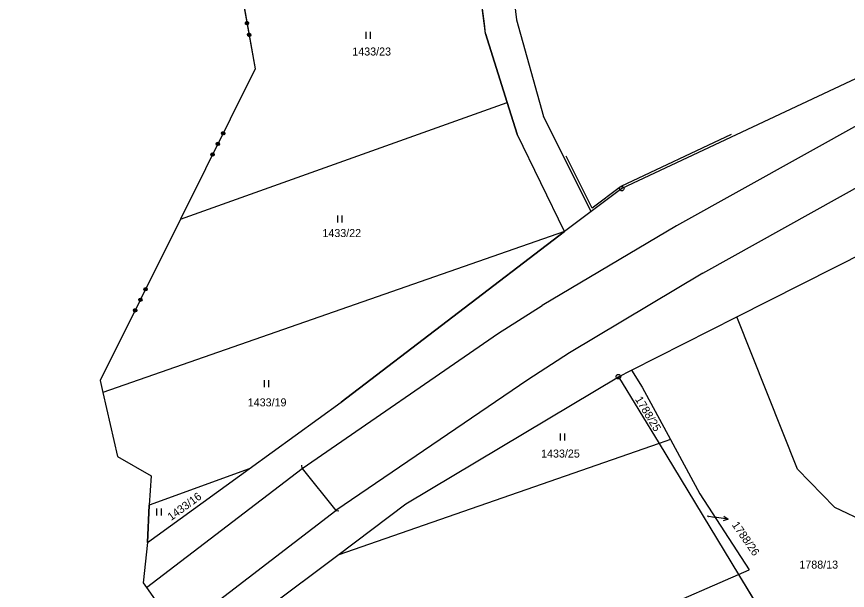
# Model space of a CAD drawing. Extents: x -779618 to -776429, y -1144546 to -1143350.
# Drawn here: x -779432.2 to -779255.7, y -1144160.9 to -1144039.1 of the extents above; entities that cross this region are included whole.
import ezdxf

# ---------------------------------------------------------------- set-up
doc = ezdxf.new("R2010")
doc.units = 0
for name, color, linetype in [('1', 7, 'Continuous'), ('11', 7, 'Continuous'), ('2', 7, 'Continuous'), ('3', 7, 'Continuous'), ('4', 7, 'Continuous'), ('7', 7, 'Continuous'), ('8', 7, 'Continuous')]:
    doc.layers.add(name, color=color, linetype=linetype)

msp = doc.modelspace()

# ---------------------------------------------------------------- linework, layer by layer
at = {"layer": '1'}
for p, q in [((-779333.51, -1143976.87), (-779326.02, -1144039.78)), ((-779332.56, -1144042.69), (-779336.07, -1144016.19)), ((-779384.98, -1144030.81), (-779381.47, -1144050.15)), ((-779326.02, -1144039.78), (-779320.25, -1144060.29)), ((-779332.56, -1144042.69), (-779327.95, -1144057.32)), ((-779234.67, -1144043.21), (-779303.65, -1144075.6)), ((-779381.47, -1144050.15), (-779397.35, -1144082.06)), ((-779397.35, -1144082.06), (-779327.95, -1144057.32)), ((-779327.95, -1144057.32), (-779325.83, -1144064.06)), ((-779310.15, -1144080.49), (-779320.25, -1144060.29)), ((-779315.83, -1144084.67), (-779325.83, -1144064.06)), ((-779303.65, -1144075.6), (-779310.15, -1144080.49)), ((-779310.15, -1144080.49), (-779315.83, -1144084.67)), ((-779279.24, -1144102.79), (-779234.73, -1144080.35)), ((-779397.35, -1144082.06), (-779414.4, -1144116.33)), ((-779315.83, -1144084.67), (-779413.82, -1144118.91)), ((-779315.83, -1144084.67), (-779363.24, -1144120.96)), ((-779301.59, -1144114.13), (-779279.24, -1144102.79)), ((-779266.31, -1144135.17), (-779279.24, -1144102.79)), ((-779304.36, -1144115.54), (-779301.59, -1144114.13)), ((-779301.59, -1144114.13), (-779299.29, -1144117.79)), ((-779349.51, -1144142.56), (-779304.36, -1144115.54)), ((-779304.36, -1144115.54), (-779295.74, -1144129.72)), ((-779414.4, -1144116.33), (-779413.82, -1144118.91)), ((-779299.29, -1144117.79), (-779293.27, -1144128.86)), ((-779413.82, -1144118.91), (-779410.76, -1144132.47)), ((-779382.76, -1144135.1), (-779363.24, -1144120.96)), ((-779295.74, -1144129.72), (-779363.98, -1144153.41)), ((-779293.27, -1144128.86), (-779295.74, -1144129.72)), ((-779295.74, -1144129.72), (-779278.85, -1144157.52)), ((-779293.27, -1144128.86), (-779287.1, -1144140.44)), ((-779410.76, -1144132.47), (-779403.56, -1144136.6)), ((-779404.34, -1144150.72), (-779382.76, -1144135.1)), ((-779382.76, -1144135.1), (-779404.03, -1144142.84)), ((-779266.31, -1144135.17), (-779258.5, -1144143.27)), ((-779403.56, -1144136.6), (-779404.03, -1144142.84)), ((-779287.1, -1144140.44), (-779276.58, -1144156.53)), ((-779363.98, -1144153.41), (-779349.51, -1144142.56)), ((-779404.34, -1144150.72), (-779404.03, -1144142.84)), ((-779258.5, -1144143.27), (-779243.97, -1144150.07)), ((-779404.34, -1144150.72), (-779405.26, -1144159.28)), ((-779393.54, -1144175.59), (-779363.98, -1144153.41)), ((-779278.85, -1144157.52), (-779276.58, -1144156.53)), ((-779298.22, -1144165.96), (-779278.85, -1144157.52)), ((-779278.85, -1144157.52), (-779271.48, -1144169.65)), ((-779405.26, -1144159.28), (-779404.55, -1144160.27)), ((-779404.55, -1144160.27), (-779398.38, -1144169.05))]:
    msp.add_line(p, q, dxfattribs=at)
for points in [[(-779382.89, -1144040.56), (-779383.04, -1144040.78), (-779383.3, -1144040.83), (-779383.52, -1144040.68), (-779383.57, -1144040.41), (-779383.42, -1144040.19), (-779383.15, -1144040.14), (-779382.93, -1144040.29), (-779382.89, -1144040.56), (-779382.93, -1144040.56), (-779382.97, -1144040.32), (-779383.06, -1144040.26), (-779382.99, -1144040.65), (-779383.06, -1144040.74), (-779383.16, -1144040.19), (-779383.23, -1144040.21), (-779383.13, -1144040.76), (-779383.21, -1144040.77), (-779383.31, -1144040.22), (-779383.39, -1144040.24), (-779383.29, -1144040.79), (-779383.38, -1144040.72), (-779383.46, -1144040.33), (-779383.52, -1144040.42), (-779383.48, -1144040.66)], [(-779382.44, -1144043.03), (-779382.59, -1144043.25), (-779382.86, -1144043.3), (-779383.08, -1144043.15), (-779383.12, -1144042.88), (-779382.97, -1144042.66), (-779382.71, -1144042.61), (-779382.48, -1144042.76), (-779382.44, -1144043.03), (-779382.48, -1144043), (-779382.53, -1144042.76), (-779382.62, -1144042.72), (-779382.55, -1144043.09), (-779382.61, -1144043.18), (-779382.7, -1144042.67), (-779382.78, -1144042.69), (-779382.69, -1144043.2), (-779382.77, -1144043.21), (-779382.86, -1144042.7), (-779382.94, -1144042.71), (-779382.85, -1144043.22), (-779382.94, -1144043.19), (-779383.01, -1144042.79), (-779383.08, -1144042.85), (-779383.04, -1144043.09)], [(-779388.07, -1144064.13), (-779388.32, -1144064.21), (-779388.56, -1144064.09), (-779388.65, -1144063.84), (-779388.53, -1144063.59), (-779388.28, -1144063.51), (-779388.03, -1144063.63), (-779387.95, -1144063.88), (-779388.07, -1144064.13), (-779388.11, -1144064.12), (-779388, -1144063.9), (-779388.04, -1144063.79), (-779388.22, -1144064.15), (-779388.31, -1144064.17), (-779388.07, -1144063.69), (-779388.15, -1144063.65), (-779388.38, -1144064.13), (-779388.46, -1144064.1), (-779388.22, -1144063.62), (-779388.29, -1144063.59), (-779388.53, -1144064.06), (-779388.58, -1144063.98), (-779388.39, -1144063.6), (-779388.49, -1144063.63), (-779388.61, -1144063.88)], [(-779389.19, -1144066.37), (-779389.44, -1144066.46), (-779389.68, -1144066.34), (-779389.77, -1144066.08), (-779389.65, -1144065.84), (-779389.39, -1144065.76), (-779389.15, -1144065.88), (-779389.07, -1144066.13), (-779389.19, -1144066.37), (-779389.22, -1144066.35), (-779389.11, -1144066.13), (-779389.15, -1144066.02), (-779389.32, -1144066.38), (-779389.43, -1144066.42), (-779389.18, -1144065.92), (-779389.25, -1144065.88), (-779389.5, -1144066.38), (-779389.57, -1144066.35), (-779389.33, -1144065.85), (-779389.4, -1144065.81), (-779389.65, -1144066.31), (-779389.68, -1144066.2), (-779389.5, -1144065.85), (-779389.61, -1144065.88), (-779389.72, -1144066.1)], [(-779390.3, -1144068.62), (-779390.56, -1144068.71), (-779390.8, -1144068.59), (-779390.89, -1144068.33), (-779390.77, -1144068.09), (-779390.51, -1144068), (-779390.27, -1144068.12), (-779390.18, -1144068.38), (-779390.3, -1144068.62), (-779390.32, -1144068.57), (-779390.21, -1144068.35), (-779390.26, -1144068.26), (-779390.43, -1144068.6), (-779390.54, -1144068.64), (-779390.3, -1144068.17), (-779390.38, -1144068.14), (-779390.61, -1144068.6), (-779390.68, -1144068.57), (-779390.45, -1144068.1), (-779390.51, -1144068.06), (-779390.75, -1144068.52), (-779390.8, -1144068.45), (-779390.62, -1144068.08), (-779390.71, -1144068.09), (-779390.82, -1144068.31)], [(-779404.53, -1144097.22), (-779404.79, -1144097.3), (-779405.03, -1144097.18), (-779405.12, -1144096.93), (-779405, -1144096.68), (-779404.74, -1144096.6), (-779404.5, -1144096.72), (-779404.41, -1144096.97), (-779404.53, -1144097.22), (-779404.57, -1144097.21), (-779404.47, -1144096.99), (-779404.5, -1144096.88), (-779404.68, -1144097.24), (-779404.78, -1144097.26), (-779404.54, -1144096.78), (-779404.61, -1144096.74), (-779404.85, -1144097.22), (-779404.92, -1144097.19), (-779404.69, -1144096.71), (-779404.76, -1144096.68), (-779404.99, -1144097.15), (-779405.04, -1144097.07), (-779404.85, -1144096.69), (-779404.95, -1144096.72), (-779405.08, -1144096.97)], [(-779405.65, -1144099.46), (-779405.91, -1144099.55), (-779406.15, -1144099.43), (-779406.23, -1144099.17), (-779406.11, -1144098.93), (-779405.86, -1144098.85), (-779405.62, -1144098.97), (-779405.53, -1144099.22), (-779405.65, -1144099.46), (-779405.68, -1144099.44), (-779405.58, -1144099.22), (-779405.61, -1144099.11), (-779405.79, -1144099.47), (-779405.9, -1144099.51), (-779405.65, -1144099.01), (-779405.72, -1144098.97), (-779405.97, -1144099.47), (-779406.04, -1144099.44), (-779405.79, -1144098.94), (-779405.86, -1144098.9), (-779406.11, -1144099.4), (-779406.15, -1144099.29), (-779405.97, -1144098.94), (-779406.08, -1144098.97), (-779406.18, -1144099.19)], [(-779406.77, -1144101.71), (-779407.02, -1144101.8), (-779407.26, -1144101.68), (-779407.35, -1144101.42), (-779407.23, -1144101.18), (-779406.98, -1144101.09), (-779406.73, -1144101.21), (-779406.65, -1144101.47), (-779406.77, -1144101.71), (-779406.79, -1144101.66), (-779406.68, -1144101.44), (-779406.72, -1144101.35), (-779406.89, -1144101.69), (-779407, -1144101.73), (-779406.77, -1144101.26), (-779406.84, -1144101.23), (-779407.07, -1144101.69), (-779407.14, -1144101.66), (-779406.91, -1144101.19), (-779406.98, -1144101.15), (-779407.21, -1144101.61), (-779407.27, -1144101.54), (-779407.08, -1144101.17), (-779407.18, -1144101.18), (-779407.28, -1144101.4)]]:
    msp.add_lwpolyline(points, dxfattribs=at)
at = {"layer": '11'}
for points in [[(-779404.34, -1144150.72), (-779382.76, -1144135.1), (-779363.24, -1144120.96), (-779315.83, -1144084.67), (-779325.83, -1144064.06), (-779327.95, -1144057.32), (-779332.56, -1144042.69), (-779332.83, -1144040.63), (-779336.07, -1144016.19), (-779336.17, -1144015.43), (-779340.84, -1143980.16), (-779340.66, -1143975.23), (-779339.55, -1143944.3), (-779339.29, -1143937.03), (-779338.46, -1143911.95), (-779338.4, -1143910.26), (-779341.38, -1143885.72), (-779341.68, -1143883.21), (-779343.67, -1143875.8), (-779348.13, -1143856.23), (-779352.41, -1143837.45), (-779358.84, -1143809.21), (-779360.96, -1143799.38), (-779367.2, -1143770.5)], [(-779432.16, -1143945.16), (-779432.02, -1143945.88), (-779431.56, -1143948.18), (-779429.86, -1143956.73), (-779425.65, -1143968.92), (-779424.83, -1143971.28), (-779418.02, -1143990.97), (-779414.5, -1143996.7), (-779411.83, -1144001.03), (-779395.93, -1144012.11), (-779385.16, -1144029.84), (-779384.98, -1144030.81), (-779381.47, -1144050.15), (-779397.35, -1144082.06), (-779414.4, -1144116.33), (-779413.82, -1144118.91), (-779410.76, -1144132.47), (-779403.56, -1144136.6), (-779404.03, -1144142.84), (-779404.34, -1144150.72)], [(-779393.54, -1144175.59), (-779363.98, -1144153.41), (-779349.51, -1144142.56), (-779304.36, -1144115.54), (-779295.74, -1144129.72), (-779278.85, -1144157.52), (-779271.57, -1144169.5), (-779271.48, -1144169.65), (-779279.8, -1144196.5), (-779281.54, -1144202.11), (-779283.19, -1144283.63), (-779292.3, -1144295.43), (-779329.76, -1144324.23)]]:
    msp.add_lwpolyline(points, dxfattribs=at)
at = {"layer": '3'}
for p, q in [((-779357.98, -1144042.28), (-779357.98, -1144043.78)), ((-779356.98, -1144043.78), (-779356.98, -1144042.28)), ((-779363.99, -1144081.28), (-779363.99, -1144082.78)), ((-779362.99, -1144082.78), (-779362.99, -1144081.28)), ((-779379.62, -1144116.29), (-779379.62, -1144117.79)), ((-779378.62, -1144117.79), (-779378.62, -1144116.29)), ((-779316.75, -1144127.6), (-779316.75, -1144129.1)), ((-779315.75, -1144129.1), (-779315.75, -1144127.6)), ((-779402.42, -1144143.51), (-779402.42, -1144145.01)), ((-779401.42, -1144145.01), (-779401.42, -1144143.51))]:
    msp.add_line(p, q, dxfattribs=at)
at = {"layer": '4'}
for p, q in [((-779251.7, -1144061.06), (-779292.02, -1144083.5)), ((-779280.41, -1144064.13), (-779303.86, -1144075.15)), ((-779309.96, -1144079.72), (-779315.49, -1144068.68)), ((-779286.43, -1144093.55), (-779246.64, -1144071.39)), ((-779303.95, -1144075.2), (-779309.96, -1144079.72)), ((-779292.02, -1144083.5), (-779320.54, -1144100.41)), ((-779286.43, -1144093.55), (-779314.74, -1144110.46)), ((-779329.79, -1144106.3), (-779320.54, -1144100.41)), ((-779371.51, -1144135.05), (-779329.79, -1144106.3)), ((-779314.74, -1144110.46), (-779323.61, -1144116.19)), ((-779323.61, -1144116.19), (-779364.4, -1144143.94)), ((-779404.55, -1144160.27), (-779371.51, -1144135.05)), ((-779371.51, -1144135.05), (-779371.58, -1144134.35)), ((-779371.51, -1144135.05), (-779364.4, -1144143.94)), ((-779397.92, -1144169.67), (-779364.4, -1144143.94)), ((-779364.4, -1144143.94), (-779363.7, -1144144.01))]:
    msp.add_line(p, q, dxfattribs=at)
at = {"layer": '7'}
for p in [(-779285.53, -1144145.1), (-779281.05, -1144145.8)]:
    msp.add_line(p, (-779284.01, -1144145.34), dxfattribs=at)
msp.add_lwpolyline([(-779281.96, -1144145.16), (-779281.05, -1144145.8), (-779282.11, -1144146.14)], dxfattribs=at)
at = {"layer": '8'}
for p, q in [((-779303.77, -1144075.6), (-779303.53, -1144075.6)), ((-779304.48, -1144115.54), (-779304.24, -1144115.54))]:
    msp.add_line(p, q, dxfattribs=at)
for points in [[(-779303.5, -1144075.12), (-779303.25, -1144075.3), (-779303.15, -1144075.59), (-779303.25, -1144075.88), (-779303.5, -1144076.06), (-779303.81, -1144076.06), (-779304.06, -1144075.88), (-779304.16, -1144075.59), (-779304.06, -1144075.3), (-779303.81, -1144075.12)], [(-779304.21, -1144115.06), (-779303.96, -1144115.24), (-779303.86, -1144115.53), (-779303.96, -1144115.82), (-779304.21, -1144116), (-779304.52, -1144116), (-779304.77, -1144115.82), (-779304.87, -1144115.53), (-779304.77, -1144115.24), (-779304.52, -1144115.06)]]:
    msp.add_lwpolyline(points, close=True, dxfattribs=at)

# ---------------------------------------------------------------- texts
at = {"layer": '2'}
for s, p in [('1433/23', (-779360.87, -1144047.33)), ('1433/22', (-779367.22, -1144085.88)), ('1433/19', (-779383.07, -1144121.84)), ('1433/25', (-779320.78, -1144132.71)), ('1788/13', (-779265.93, -1144156.29))]:
    msp.add_text(s, height=1.7, dxfattribs=at).set_placement(p)
for s, height, rotation, p in [('1788/25', 1.7, 301.0893, (-779300.89, -1144120.33)), ('1433/16', 1.7, 36.3828, (-779399.33, -1144146.2)), ('1788/26', 0.1, 302.2925, (-779285.52, -1144145.12))]:
    msp.add_text(s, height=height, rotation=rotation, dxfattribs=at).set_placement(p)
at = {"layer": '7'}
msp.add_text('1788/26', height=1.7, rotation=304.7563, dxfattribs=at).set_placement((-779280.34, -1144147.02))

doc.saveas('drawing.dxf')
